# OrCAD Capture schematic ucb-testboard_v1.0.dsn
size C; title: NCREPT UCB TestBoard; rev: 1.0; company: University of Arkansas (NCREPT); note: 700 W. Research Center Blvd; note: Fayetteville, AR 72701
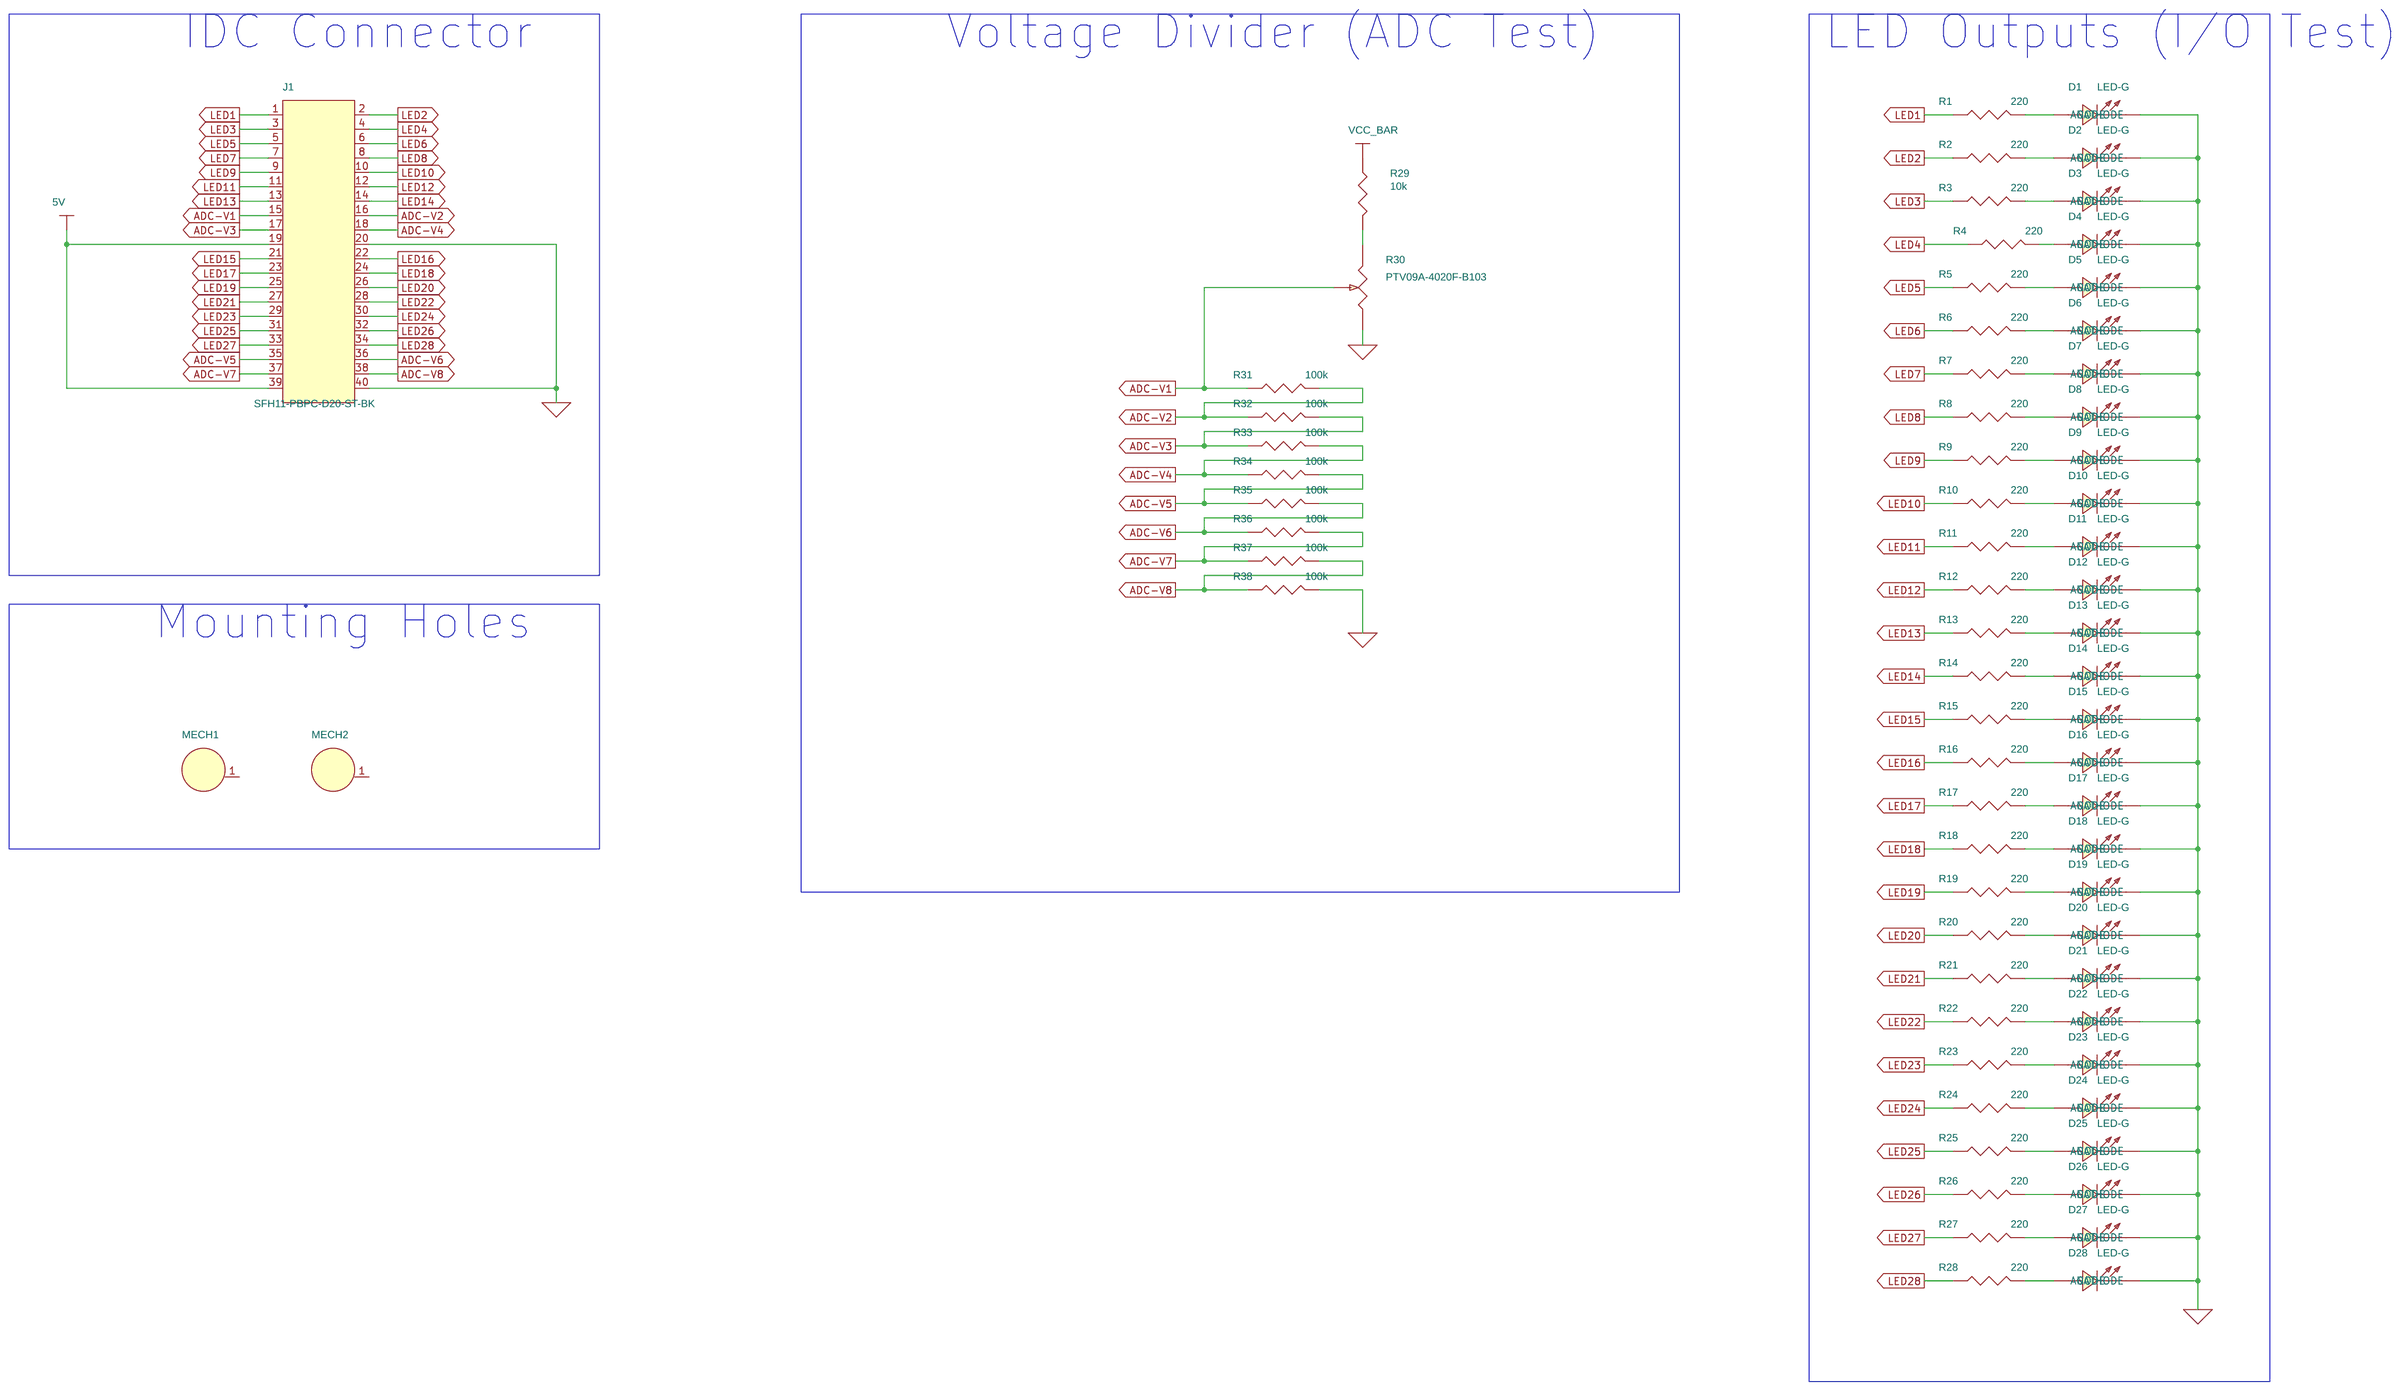
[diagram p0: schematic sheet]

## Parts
D1  LED-G  [LED_0805-GREEN]
D2  LED-G  [LED_0805-GREEN]
D3  LED-G  [LED_0805-GREEN]
D4  LED-G  [LED_0805-GREEN]
D5  LED-G  [LED_0805-GREEN]
D6  LED-G  [LED_0805-GREEN]
D7  LED-G  [LED_0805-GREEN]
D8  LED-G  [LED_0805-GREEN]
D9  LED-G  [LED_0805-GREEN]
D10  LED-G  [LED_0805-GREEN]
D11  LED-G  [LED_0805-GREEN]
D12  LED-G  [LED_0805-GREEN]
D13  LED-G  [LED_0805-GREEN]
D14  LED-G  [LED_0805-GREEN]
D15  LED-G  [LED_0805-GREEN]
D16  LED-G  [LED_0805-GREEN]
D17  LED-G  [LED_0805-GREEN]
D18  LED-G  [LED_0805-GREEN]
D19  LED-G  [LED_0805-GREEN]
D20  LED-G  [LED_0805-GREEN]
D21  LED-G  [LED_0805-GREEN]
D22  LED-G  [LED_0805-GREEN]
D23  LED-G  [LED_0805-GREEN]
D24  LED-G  [LED_0805-GREEN]
D25  LED-G  [LED_0805-GREEN]
D26  LED-G  [LED_0805-GREEN]
D27  LED-G  [LED_0805-GREEN]
D28  LED-G  [LED_0805-GREEN]
J1  SFH11-PBPC-D20-ST-BK  [40-IDC-F_MNT]
MECH1  Mech_Hole  [4-40_SCREW]
MECH2  Mech_Hole  [4-40_SCREW]
R1  220  [R_0805]
R2  220  [R_0805]
R3  220  [R_0805]
R4  220  [R_0805]
R5  220  [R_0805]
R6  220  [R_0805]
R7  220  [R_0805]
R8  220  [R_0805]
R9  220  [R_0805]
R10  220  [R_0805]
R11  220  [R_0805]
R12  220  [R_0805]
R13  220  [R_0805]
R14  220  [R_0805]
R15  220  [R_0805]
R16  220  [R_0805]
R17  220  [R_0805]
R18  220  [R_0805]
R19  220  [R_0805]
R20  220  [R_0805]
R21  220  [R_0805]
R22  220  [R_0805]
R23  220  [R_0805]
R24  220  [R_0805]
R25  220  [R_0805]
R26  220  [R_0805]
R27  220  [R_0805]
R28  220  [R_0805]
R29  10k  [R_0805]
R30  PTV09A-4020F-B103  [9MM_POT]
R31  100k  [R_0603]
R32  100k  [R_0603]
R33  100k  [R_0603]
R34  100k  [R_0603]
R35  100k  [R_0603]
R36  100k  [R_0603]
R37  100k  [R_0603]
R38  100k  [R_0603]

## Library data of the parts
D1-D28 = LED: LED, 0805, Green, VF= 2.2V; Manufacturer: OSRAM; Manufacturer_Part_Number: LG R971-KN-1; Part_Number: D-00008; STEP_Model: LED_0805-Green.stp; Datasheet: OSRAM-LGR971-CHIPLED-0805-318376.pdf
J1 = Header_2x20: 40-POS Header, Shrouded, 0.100", TH, Female w/ Mounting; Manufacturer: Sullins; Part_Number: Con-00020; Datasheet: Sullins-146_PAGE119_.100_SFH11_SERIES_FEMALE_HDR_ST_RA.pdf
MECH1 MECH2 = Mech_Hole: Mounting Hole for 4-40 Screw, 0.125"; Part_Number: Con-00005
R1-R28 = R-Standard: 220 Ohm, 1%, 0805; Manufacturer: KOA Speer; Manufacturer_Part_Number: RK73H2ATTD2200F; Part_Number: Res-00017; Rating: 0.125W; Tolerance: 1%; Datasheet: KOA-RK73H-5715.pdf
R29 = R-Standard: 10k Ohm, 1%, 0805; Manufacturer: KOA Speer; Manufacturer_Part_Number: RK73H2ATTD1002F; Part_Number: Res-00032; Tolerance: 1%; Datasheet: KOA-RK73H-5715.pdf
R30 = R-POT: Potentiometer 10k Linear, 6mm Shaft,TH; Manufacturer: Bourns; Part_Number: Res-00043; Tolerance: 20%; Datasheet: Bourns-tv09-777818.pdf
R31-R38 = R-Standard: 100k Ohm, 1%, 0603; Manufacturer: KOA Speer; Manufacturer_Part_Number: RK73H1JTTD1003F; Part_Number: TMP-220; Tolerance: 1%; Datasheet: KOA-RK73H-5715.pdf

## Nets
5V: J1.19 J1.39 R29.1
GND_SIGNAL: D1.1(CATHODE) D2.1(CATHODE) D3.1(CATHODE) D4.1(CATHODE) D5.1(CATHODE) D6.1(CATHODE) D7.1(CATHODE) D8.1(CATHODE) D9.1(CATHODE) D10.1(CATHODE) D11.1(CATHODE) D12.1(CATHODE) D13.1(CATHODE) D14.1(CATHODE) D15.1(CATHODE) D16.1(CATHODE) D17.1(CATHODE) D18.1(CATHODE) D19.1(CATHODE) D20.1(CATHODE) D21.1(CATHODE) D22.1(CATHODE) D23.1(CATHODE) D24.1(CATHODE) D25.1(CATHODE) D26.1(CATHODE) D27.1(CATHODE) D28.1(CATHODE) J1.20 J1.40 R30.1(A) R38.2
ADC-V1: J1.15 R30.2(WIPER) R31.1
ADC-V2: J1.16 R31.2 R32.1
ADC-V3: J1.17 R32.2 R33.1
ADC-V4: J1.18 R33.2 R34.1
ADC-V5: J1.35 R34.2 R35.1
ADC-V6: J1.36 R35.2 R36.1
ADC-V7: J1.37 R36.2 R37.1
ADC-V8: J1.38 R37.2 R38.1
LED1: J1.1 R1.1
LED2: J1.2 R2.1
LED3: J1.3 R3.1
LED4: J1.4 R4.1
LED5: J1.5 R5.1
LED6: J1.6 R6.1
LED7: J1.7 R7.1
LED8: J1.8 R8.1
LED9: J1.9 R9.1
LED10: J1.10 R10.1
LED11: J1.11 R11.1
LED12: J1.12 R12.1
LED13: J1.13 R13.1
LED14: J1.14 R14.1
LED15: J1.21 R15.1
LED16: J1.22 R16.1
LED17: J1.23 R17.1
LED18: J1.24 R18.1
LED19: J1.25 R19.1
LED20: J1.26 R20.1
LED21: J1.27 R21.1
LED22: J1.28 R22.1
LED23: J1.29 R23.1
LED24: J1.30 R24.1
LED25: J1.31 R25.1
LED26: J1.32 R26.1
LED27: J1.33 R27.1
LED28: J1.34 R28.1
N294916: D1.2(ANODE) R1.2
N294970: D2.2(ANODE) R2.2
N295024: D3.2(ANODE) R3.2
N295078: D4.2(ANODE) R4.2
N295138: D5.2(ANODE) R5.2
N295192: D6.2(ANODE) R6.2
N295246: D7.2(ANODE) R7.2
N295300: D8.2(ANODE) R8.2
N297354: D9.2(ANODE) R9.2
N297404: D10.2(ANODE) R10.2
N297454: D11.2(ANODE) R11.2
N297504: D12.2(ANODE) R12.2
N297554: D13.2(ANODE) R13.2
N297604: D14.2(ANODE) R14.2
N297654: D15.2(ANODE) R15.2
N297704: D16.2(ANODE) R16.2
N298162: D17.2(ANODE) R17.2
N298212: D18.2(ANODE) R18.2
N298262: D19.2(ANODE) R19.2
N298312: D20.2(ANODE) R20.2
N298362: D21.2(ANODE) R21.2
N298412: D22.2(ANODE) R22.2
N298462: D23.2(ANODE) R23.2
N298512: D24.2(ANODE) R24.2
N299934: D25.2(ANODE) R25.2
N299984: D26.2(ANODE) R26.2
N300034: D27.2(ANODE) R27.2
N300084: D28.2(ANODE) R28.2
N303443: R29.2 R30.3(B)

Not connected (* = marked no-connect by the designer): MECH1 1; MECH2 1

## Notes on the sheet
- IDC Connector
- Voltage Divider (ADC Test)
- LED Outputs (I/O Test)
- Mounting Holes
